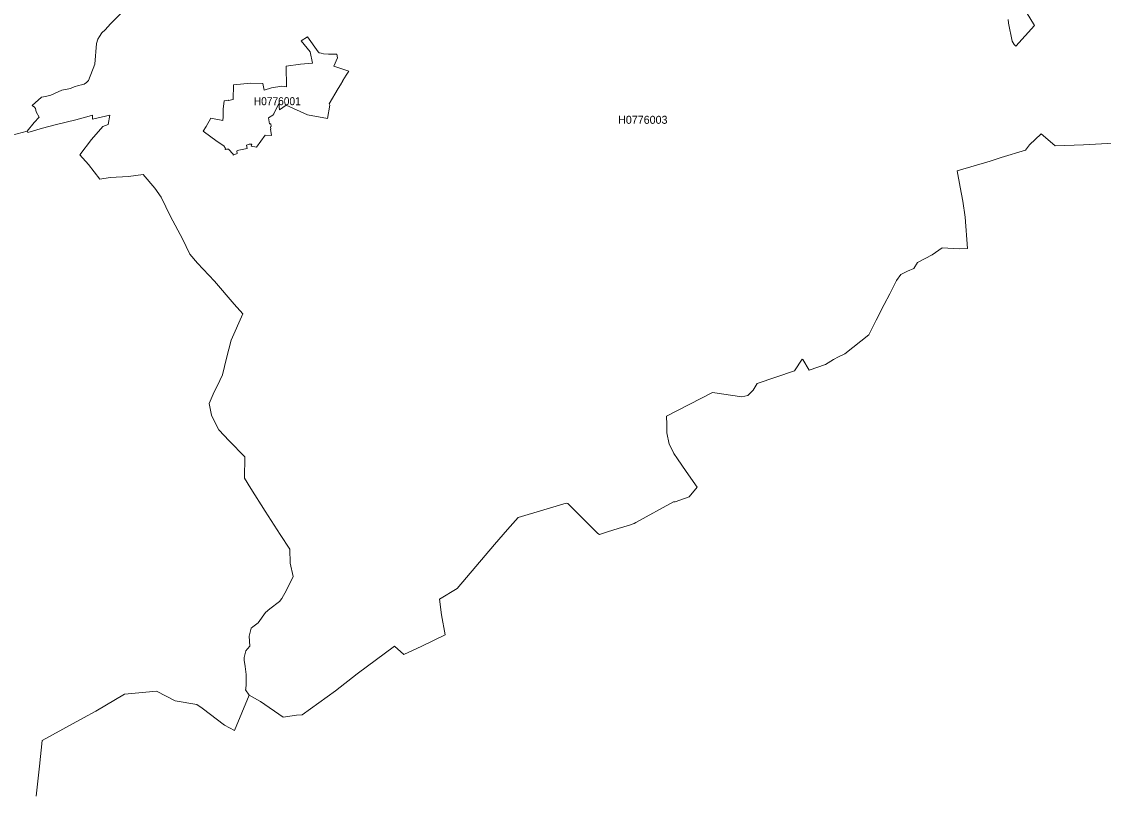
# Model space of a CAD drawing. Extents: x 369010 to 739155, y 6377141 to 6616555.
# Drawn here: x 481540 to 495056, y 6526211 to 6535866 of the extents above; entities that cross this region are included whole.
import ezdxf
from ezdxf.enums import TextEntityAlignment as Align

# ---------------------------------------------------------------- set-up
doc = ezdxf.new("R2010")
doc.units = 0
doc.header["$LTSCALE"] = 40
doc.layers.add('1', color=7, linetype='Continuous', lineweight=13)
doc.layers.add('2', color=7, linetype='Continuous')

msp = doc.modelspace()

# ---------------------------------------------------------------- linework, layer by layer
at = {"layer": '1'}
for points in [[(494000.48, 6536141.17), (494193.46, 6535819.27), (493961.59, 6535558.93), (493943.38, 6535579.12), (493916.74, 6535623.97), (493871.72, 6535848.56), (493868.41, 6535892.09)], [(493868.41, 6535892.09), (493871.72, 6535848.56), (493916.74, 6535623.97), (493943.38, 6535579.12), (493961.59, 6535558.93), (494193.46, 6535819.27), (494000.48, 6536141.17)], [(481360.28, 6534432.68), (481608.86, 6534496.4), (481695.26, 6534606.79), (481759.31, 6534672.49), (481720.75, 6534739.85), (481714.62, 6534782.22), (481700.55, 6534798.11), (481672.25, 6534816.48), (481788.27, 6534922.57), (481836.6, 6534928.69), (481905.28, 6534948.39), (482040.5, 6535009.62), (482151.55, 6535031.14), (482194.75, 6535050.17), (482248.04, 6535068.05), (482286.77, 6535075.99), (482322.85, 6535085.76), (482351.15, 6535104.13), (482374.32, 6535131.77), (482452.94, 6535332.85), (482476.11, 6535594.18), (482492.16, 6535646.81), (482512.35, 6535682.4), (482543.63, 6535727.25), (482582.19, 6535763.99), (482650.38, 6535839.46), (482781.46, 6535973.68)], [(482781.46, 6535973.68), (482650.38, 6535839.46), (482582.19, 6535763.99), (482543.63, 6535727.25), (482512.35, 6535682.4), (482492.16, 6535646.81), (482476.11, 6535594.18), (482452.94, 6535332.85), (482374.32, 6535131.77), (482351.15, 6535104.13), (482322.85, 6535085.76), (482286.77, 6535075.99), (482248.04, 6535068.05), (482194.75, 6535050.17), (482151.55, 6535031.14), (482040.5, 6535009.62), (481905.28, 6534948.39), (481836.6, 6534928.69), (481788.27, 6534922.57), (481672.25, 6534816.48), (481700.55, 6534798.11), (481714.62, 6534782.22), (481720.75, 6534739.85), (481759.31, 6534672.49), (481695.26, 6534606.79), (481608.86, 6534496.4), (481615.32, 6534481), (481801.68, 6534533.8), (481975.62, 6534579.15), (482216.43, 6534641.21), (482411.23, 6534694.5), (482426.29, 6534696.99), (482423.81, 6534649.16), (482642.11, 6534698.81), (482621.75, 6534579.81), (482553.73, 6534554.65), (482411.23, 6534393.95), (482266.74, 6534202.63), (482376.47, 6534081.81), (482518.14, 6533897.93), (482647.57, 6533917.46), (482874.8, 6533932.85), (483060.17, 6533956.69), (483202.5, 6533785.06), (483283.43, 6533674.01), (483401.44, 6533431.21), (483550.72, 6533151.51), (483643.07, 6532962.01), (483736.92, 6532849.8), (483948.76, 6532623.55), (484195.2, 6532337.07), (484302.77, 6532215.75), (484157.13, 6531885.74), (484100.53, 6531663.13), (484048.39, 6531452.28), (483984.18, 6531312.93), (483944.46, 6531242.42), (483883.72, 6531094.63), (483912.18, 6530948.65), (483957.04, 6530851.83), (484002.88, 6530765.77), (484131.31, 6530629.89), (484330.25, 6530429.63), (484322.8, 6530161.52), (484404.89, 6530031.26), (484584.46, 6529750.07), (484769.16, 6529456.14), (484891.97, 6529274.41), (484896.93, 6529100.14), (484932.85, 6528935.3), (484848.11, 6528761.02), (484789.69, 6528657.25), (484763.54, 6528622.16), (484640.07, 6528528.16), (484585.12, 6528483.97), (484496.58, 6528355.54), (484428.72, 6528304.39), (484409.19, 6528289.33), (484383.7, 6528189.04), (484390.49, 6528062.76), (484363.35, 6528029.49), (484339.85, 6528003.84), (484326.44, 6527955.02), (484321.31, 6527920.59), (484320.32, 6527886.17)], [(484321.31, 6527920.59), (484326.44, 6527955.02), (484339.85, 6528003.84), (484363.35, 6528029.49), (484390.49, 6528062.76), (484383.7, 6528189.04), (484409.19, 6528289.33), (484428.72, 6528304.39), (484496.58, 6528355.54), (484585.12, 6528483.97), (484640.07, 6528528.16), (484763.54, 6528622.16), (484789.69, 6528657.25), (484848.11, 6528761.02), (484932.85, 6528935.3), (484896.93, 6529100.14), (484891.97, 6529274.41), (484769.16, 6529456.14), (484584.46, 6529750.07), (484404.89, 6530031.26), (484322.8, 6530161.52), (484330.25, 6530429.63), (484131.31, 6530629.89), (484002.88, 6530765.77), (483957.04, 6530851.83), (483912.18, 6530948.65), (483883.72, 6531094.63), (483944.46, 6531242.42), (483984.18, 6531312.93), (484048.39, 6531452.28), (484100.53, 6531663.13), (484157.13, 6531885.74), (484302.77, 6532215.75), (484195.2, 6532337.07), (483948.76, 6532623.55), (483736.92, 6532849.8), (483643.07, 6532962.01), (483550.72, 6533151.51), (483401.44, 6533431.21), (483283.43, 6533674.01), (483202.5, 6533785.06), (483060.17, 6533956.69), (482874.8, 6533932.85), (482647.57, 6533917.46), (482518.14, 6533897.93), (482376.47, 6534081.81), (482266.74, 6534202.63), (482411.23, 6534393.95), (482553.73, 6534554.65), (482621.75, 6534579.81), (482642.11, 6534698.81), (482423.81, 6534649.16), (482426.29, 6534696.99), (482411.23, 6534694.5), (482216.43, 6534641.21), (481975.62, 6534579.15), (481801.68, 6534533.8), (481615.32, 6534481), (481608.86, 6534496.4)], [(481608.86, 6534496.4), (481360.28, 6534432.68)], [(495487.7, 6534363.5), (494805.66, 6534328.57), (494455.45, 6534313.35), (494418.38, 6534343.97), (494278.36, 6534463.63), (494132.39, 6534327.25), (494083.56, 6534261.88), (493777.22, 6534168.2), (493641.34, 6534124.51), (493229.73, 6534000.05), (493268.29, 6533796.98), (493298.58, 6533623.36), (493330.69, 6533422.11), (493357.66, 6533031.52), (493260.35, 6533029.2), (493040.89, 6533041.78), (492916.26, 6532950.75), (492732.89, 6532854.6), (492688.53, 6532780.78), (492608.76, 6532749.17), (492526.67, 6532706.8), (492470.4, 6532629.84), (492385.99, 6532464.34), (492316.15, 6532330.11), (492217.51, 6532135.15), (492123.83, 6531954.42), (491824.93, 6531716.43), (491745.65, 6531679.02), (491681.93, 6531642.94), (491582.3, 6531580.71), (491378.23, 6531511.7), (491300.45, 6531644.6), (491292.83, 6531648.73), (491197.34, 6531504.41), (490730.12, 6531343.38), (490679.48, 6531262.78), (490611.45, 6531195.25), (490536.48, 6531179.86), (490170.22, 6531234.31), (489598.57, 6530935.74), (489599.73, 6530831.81), (489602.71, 6530726.88), (489631.84, 6530586.03), (489670.56, 6530509.57), (489688.27, 6530470.01), (489735.94, 6530402.65), (489842.85, 6530244.27), (489978.73, 6530049.14), (489882.08, 6529928.15), (489705.82, 6529865.76), (489683.14, 6529866.09), (489214.27, 6529607.08), (489193.75, 6529594), (489136.65, 6529574.8), (488994.65, 6529531.28), (488860.92, 6529489.73), (488761.12, 6529456.8), (488739.27, 6529472.19), (488696.74, 6529513.73), (488486.88, 6529723.76), (488366.06, 6529847.06), (488345.04, 6529849.87), (487742.28, 6529669.47), (487609.38, 6529520.68), (487446.03, 6529331.35), (486981.46, 6528785.02), (486759.85, 6528648.81), (486787.65, 6528452.69), (486829.85, 6528204.26), (486539.23, 6528060.94), (486315.8, 6527959.48), (486199.28, 6528063.59), (485731.57, 6527715.53), (485459.65, 6527504.35), (485044.89, 6527206.61), (484972.9, 6527201.15), (484808.72, 6527176.98), (484522.89, 6527370.95), (484382.71, 6527451.22), (484197.68, 6527009), (484073.55, 6527075.03), (483795.01, 6527287.04), (483727.65, 6527333.88), (483459.53, 6527378.4)], [(484320.32, 6527886.17), (484330.91, 6527809.87), (484346.47, 6527710.07), (484345.47, 6527585.61), (484342, 6527527.85), (484335.71, 6527516.1), (484382.71, 6527451.22), (484522.89, 6527370.95), (484808.72, 6527176.98), (484972.9, 6527201.15), (485044.89, 6527206.61), (485459.65, 6527504.35), (485731.57, 6527715.53), (486199.28, 6528063.59), (486315.8, 6527959.48), (486539.23, 6528060.94), (486829.85, 6528204.26), (486787.65, 6528452.69), (486759.85, 6528648.81), (486981.46, 6528785.02), (487446.03, 6529331.35), (487609.38, 6529520.68), (487742.28, 6529669.47), (488345.04, 6529849.87), (488366.06, 6529847.06), (488486.88, 6529723.76), (488696.74, 6529513.73), (488739.27, 6529472.19), (488761.12, 6529456.8), (488860.92, 6529489.73), (488994.65, 6529531.28), (489136.65, 6529574.8), (489193.75, 6529594), (489214.27, 6529607.08), (489683.14, 6529866.09), (489705.82, 6529865.76), (489882.08, 6529928.15), (489978.73, 6530049.14), (489842.85, 6530244.27), (489735.94, 6530402.65), (489688.27, 6530470.01), (489670.56, 6530509.57), (489631.84, 6530586.03), (489602.71, 6530726.88), (489599.73, 6530831.81), (489598.57, 6530935.74), (490170.22, 6531234.31), (490536.48, 6531179.86), (490611.45, 6531195.25), (490679.48, 6531262.78), (490730.12, 6531343.38), (491197.34, 6531504.41), (491292.83, 6531648.73), (491300.45, 6531644.6), (491378.23, 6531511.7), (491582.3, 6531580.71), (491681.93, 6531642.94), (491745.65, 6531679.02), (491824.93, 6531716.43), (492123.83, 6531954.42), (492217.51, 6532135.15), (492316.15, 6532330.11), (492385.99, 6532464.34), (492470.4, 6532629.84), (492526.67, 6532706.8), (492608.76, 6532749.17), (492688.53, 6532780.78), (492732.89, 6532854.6), (492916.26, 6532950.75), (493040.89, 6533041.78), (493260.35, 6533029.2), (493357.66, 6533031.52), (493330.69, 6533422.11), (493298.58, 6533623.36), (493268.29, 6533796.98), (493229.73, 6534000.05), (493641.34, 6534124.51), (493777.22, 6534168.2), (494083.56, 6534261.88), (494132.39, 6534327.25), (494278.36, 6534463.63), (494418.38, 6534343.97), (494455.45, 6534313.35), (494805.66, 6534328.57), (495487.7, 6534363.5)], [(481722.24, 6526190.41), (481764.6, 6526562.96), (481797.7, 6526884.2), (482312.26, 6527167.05), (482466.84, 6527251.13), (482825.15, 6527462.48), (483223.85, 6527502.53), (483459.53, 6527378.4), (483727.65, 6527333.88), (483795.01, 6527287.04), (484073.55, 6527075.03), (484197.68, 6527009), (484382.71, 6527451.22), (484335.71, 6527516.1), (484342, 6527527.85), (484345.47, 6527585.61), (484346.47, 6527710.07), (484330.91, 6527809.87), (484320.32, 6527886.17), (484321.31, 6527920.59)], [(483459.53, 6527378.4), (483223.85, 6527502.53), (482825.15, 6527462.48), (482466.84, 6527251.13), (482312.26, 6527167.05), (481797.7, 6526884.2), (481764.6, 6526562.96), (481722.24, 6526190.41)]]:
    msp.add_lwpolyline(points, dxfattribs=at)
for points in [[(484186.42, 6535076.32), (484402.08, 6535099.33), (484554.67, 6535093.87), (484568.08, 6535011.11), (484662.08, 6535037.1), (484792.33, 6535060.1), (484848.27, 6535050.67), (484844.63, 6535308.03), (485023.71, 6535335.17), (485174.15, 6535347.09), (485143.86, 6535489.42), (485032.15, 6535626.79), (485112.09, 6535675.78), (485243.5, 6535488.43), (485257.57, 6535477.67), (485281.07, 6535470.55), (485312.51, 6535465.75), (485373.58, 6535461.28), (485478.35, 6535459.63), (485486.95, 6535411.96), (485440.78, 6535310.68), (485627.14, 6535245.63), (485595.36, 6535195.32), (485554.31, 6535129.95), (485554.98, 6535124.48), (485525.02, 6535075.49), (485495.4, 6535031.14), (485380.54, 6534838), (485389.8, 6534822.11), (485362.99, 6534657.43), (485110.76, 6534701.62), (484844.96, 6534823.27), (484763.21, 6534763.35), (484752.45, 6534842.63), (484692.04, 6534715.69), (484677.14, 6534696.82), (484625.51, 6534662.73), (484638.25, 6534587.59), (484651.82, 6534589.41), (484656.29, 6534556.64), (484649.17, 6534551.18), (484653.64, 6534520.56), (484647.52, 6534521.06), (484659.77, 6534442.28), (484582.81, 6534449.23), (484473.9, 6534299.61), (484407.37, 6534312.02), (484414.82, 6534333.21), (484384.37, 6534333.71), (484349.94, 6534323.78), (484356.23, 6534280.58), (484230.61, 6534255.26), (484226.81, 6534249.46), (484233.1, 6534219.84), (484183.78, 6534197.16), (484182.45, 6534210.4), (484122.37, 6534272.3), (484098.38, 6534273.96), (484088.61, 6534267.83), (484081.16, 6534274.12), (484087.29, 6534281.74), (484064.61, 6534314.18), (483983.35, 6534367.3), (483806.59, 6534499.21), (483843.5, 6534556.47), (483904.74, 6534660.41), (484055.51, 6534630.95), (484057.33, 6534677.95), (484056.34, 6534774.44), (484071.23, 6534874.74), (484121.05, 6534885.83), (484123.53, 6534878.88), (484183.28, 6534894.43)], [(484186.42, 6535076.32), (484183.28, 6534894.43), (484123.53, 6534878.88), (484121.05, 6534885.83), (484071.23, 6534874.74), (484056.34, 6534774.44), (484057.33, 6534677.95), (484055.51, 6534630.95), (483904.74, 6534660.41), (483843.5, 6534556.47), (483806.59, 6534499.21), (483983.35, 6534367.3), (484064.61, 6534314.18), (484087.29, 6534281.74), (484081.16, 6534274.12), (484088.61, 6534267.83), (484098.38, 6534273.96), (484122.37, 6534272.3), (484182.45, 6534210.4), (484183.78, 6534197.16), (484233.1, 6534219.84), (484226.81, 6534249.46), (484230.61, 6534255.26), (484356.23, 6534280.58), (484349.94, 6534323.78), (484384.37, 6534333.71), (484414.82, 6534333.21), (484407.37, 6534312.02), (484473.9, 6534299.61), (484582.81, 6534449.23), (484659.77, 6534442.28), (484647.52, 6534521.06), (484653.64, 6534520.56), (484649.17, 6534551.18), (484656.29, 6534556.64), (484651.82, 6534589.41), (484638.25, 6534587.59), (484625.51, 6534662.73), (484677.14, 6534696.82), (484692.04, 6534715.69), (484752.45, 6534842.63), (484763.21, 6534763.35), (484844.96, 6534823.27), (485110.76, 6534701.62), (485362.99, 6534657.43), (485389.8, 6534822.11), (485380.54, 6534838), (485495.4, 6535031.14), (485525.02, 6535075.49), (485554.98, 6535124.48), (485554.31, 6535129.95), (485595.36, 6535195.32), (485627.14, 6535245.63), (485440.78, 6535310.68), (485486.95, 6535411.96), (485478.35, 6535459.63), (485373.58, 6535461.28), (485312.51, 6535465.75), (485281.07, 6535470.55), (485257.57, 6535477.67), (485243.5, 6535488.43), (485112.09, 6535675.78), (485032.15, 6535626.79), (485143.86, 6535489.42), (485174.15, 6535347.09), (485023.71, 6535335.17), (484844.63, 6535308.03), (484848.27, 6535050.67), (484792.33, 6535060.1), (484662.08, 6535037.1), (484568.08, 6535011.11), (484554.67, 6535093.87), (484402.08, 6535099.33)]]:
    msp.add_lwpolyline(points, close=True, dxfattribs=at)

# ---------------------------------------------------------------- texts
at = {"layer": '2', "width": 0.95}
msp.add_text('H0776001', height=100, dxfattribs=at).set_placement((484734.06, 6534822.18), align=Align.CENTER)
at = {"layer": '2'}
msp.add_text('H0776003', height=100, dxfattribs=at).set_placement((489301.03, 6534589.64), align=Align.CENTER)

doc.saveas('drawing.dxf')
